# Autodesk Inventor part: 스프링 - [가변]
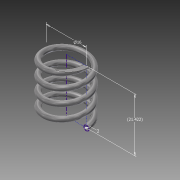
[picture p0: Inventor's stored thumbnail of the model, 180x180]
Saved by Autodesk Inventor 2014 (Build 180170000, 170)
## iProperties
Created: 2015-04
Part Number: 스프링 - [가변]
Material: 강철, 탄소
Document SubType Name: Modeling
Designer: basic
Mass: 4.87376 g
Surface Area: 12.6179 cm^2
Volume: 0.619283 cm^3
Density: 7.87 g/cm^3
Appearance: 반연마
Author: basic
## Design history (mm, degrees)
sketch "스케치1"
  geometry: L1 (0, 0)-(-8, 0); L2 (-8, 0)-(-8, 21.422); L3 (-8, 21.422)-(0, 21.422); L4 (0, 21.422)-(0, 0); C1 r 1 at (-8, 0)
  constraints: 8 end point, 2 parallel, 1 centre point, 1 coincident, 1 horizontal, 1 perpendicular
  dimensions: "d0" = 2 diameter of C1; "d1" = 21.42196 distance between parallel lines of L1 L3 (derived); "d2" = 16 diameter of L2 L4
feature "코일1" sketch "스케치1" pitch "d3" = 10; turns "d5" = 4; dims "d4" = 21.42196 (= d1), "d6" = 0, angle "d7" = 90 deg, angle "d8" = 90 deg, "d9" = 0, "d10" = 0
sketch "스케치2"
  geometry: L1 (9, 0)-(7, 0) reference; 1 further point
  constraints: 1 horizontal alignment
extrude "돌출1" cut sketch "스케치2" distance "d11" = 10; taper "d12" = 0 deg
node "작업 평면1"
sketch "스케치3"
  geometry: L1 (1, 0)-(-1, 0) reference; 1 further point
  constraints: 1 horizontal alignment
extrude "돌출2" cut sketch "스케치3" distance "d14" = 10; taper "d15" = 0 deg
node "솔리드1"
node "절단 모서리 투영1"
node "절단 모서리 투영2"
other parameters: "d13" = 0
